// Mitsubishi GX Works2 project: MC-17MR-14MTS-F350-FX-B   PLC: FX1S

PROGRAM MAIN
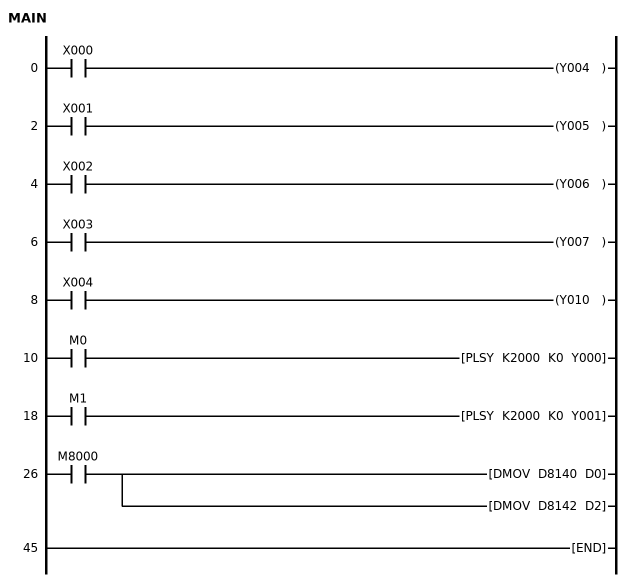
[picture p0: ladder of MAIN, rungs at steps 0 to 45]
0     LD      X000
      OUT     Y004
2     LD      X001
      OUT     Y005
4     LD      X002
      OUT     Y006
6     LD      X003
      OUT     Y007
8     LD      X004
      OUT     Y010
10    LD      M0
      PLSY    K2000 K0 Y000
18    LD      M1
      PLSY    K2000 K0 Y001
26    LD      M8000
      DMOV    D8140 D0
      DMOV    D8142 D2
45    END
END_PROGRAM
